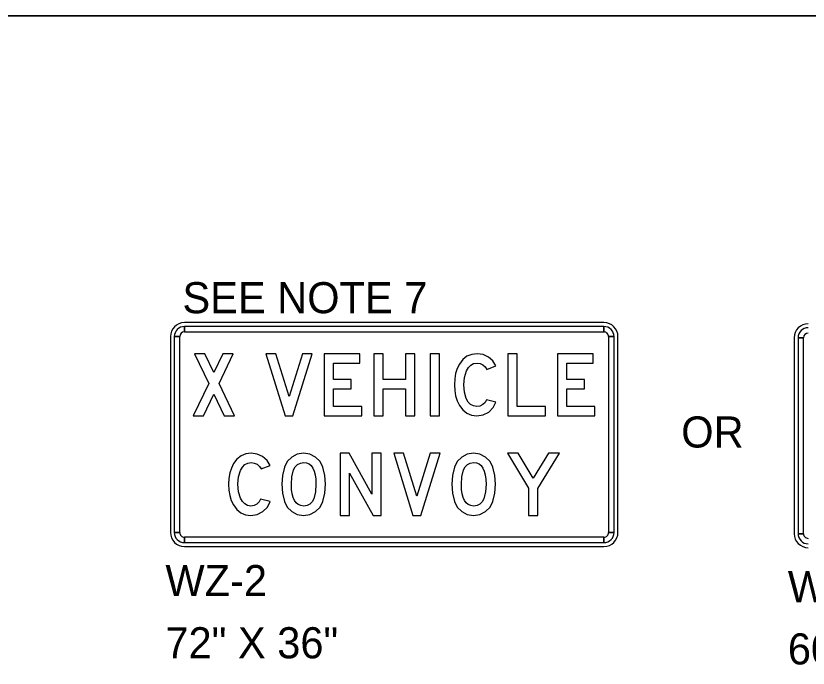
# Model space of a CAD drawing. Extents: x 1374027 to 1374537, y 380415 to 381405.
# Drawn here: x 1374115.53 to 1374130.82, y 381392.59 to 381405.17 of the extents above; entities that cross this region are included whole.
import ezdxf

# ---------------------------------------------------------------- set-up
doc = ezdxf.new("R2010")
doc.units = 0
doc.layers.add('DSN_DRFT_Junk-No-Plot', color=7, linetype='Continuous')
doc.layers.add('Working Level 1', color=7, linetype='Continuous')

msp = doc.modelspace()

# ---------------------------------------------------------------- linework, layer by layer
at = {"layer": 'DSN_DRFT_Junk-No-Plot'}
for points in [[(1374027.083, 381405.174), (1374197.083, 381405.174), (1374197.083, 381295.174), (1374027.083, 381295.174)], [(1374027.083, 381405.174), (1374027.083, 381295.174), (1374197.083, 381295.174), (1374197.083, 381405.174)]]:
    msp.add_lwpolyline(points, close=True, dxfattribs=at)
at = {"layer": 'Working Level 1'}
for p, q in [((1374126.884, 381399.254), (1374118.785, 381399.254)), ((1374118.785, 381399.074), (1374118.785, 381399.179)), ((1374126.884, 381399.179), (1374126.884, 381399.074)), ((1374118.515, 381398.984), (1374118.515, 381395.204)), ((1374118.59, 381398.984), (1374118.695, 381398.984)), ((1374126.974, 381398.984), (1374127.079, 381398.984)), ((1374127.154, 381395.204), (1374127.154, 381398.984)), ((1374130.555, 381398.961), (1374130.555, 381395.181)), ((1374130.63, 381398.961), (1374130.735, 381398.961)), ((1374118.695, 381395.204), (1374118.59, 381395.204)), ((1374127.079, 381395.204), (1374126.974, 381395.204)), ((1374130.735, 381395.181), (1374130.63, 381395.181)), ((1374118.785, 381395.009), (1374118.785, 381395.114)), ((1374126.884, 381395.114), (1374126.884, 381395.009)), ((1374118.785, 381394.934), (1374126.884, 381394.934))]:
    msp.add_line(p, q, dxfattribs=at)
for points in [[(1374126.884, 381399.179), (1374118.785, 381399.179), (1374118.785, 381399.074), (1374126.884, 381399.074), (1374126.884, 381399.179)], [(1374118.59, 381398.984), (1374118.59, 381395.204), (1374118.695, 381395.204), (1374118.695, 381398.984), (1374118.59, 381398.984)], [(1374127.079, 381395.204), (1374127.079, 381398.984), (1374126.974, 381398.984), (1374126.974, 381395.204), (1374127.079, 381395.204)], [(1374130.63, 381398.961), (1374130.63, 381395.181), (1374130.735, 381395.181), (1374130.735, 381398.961), (1374130.63, 381398.961)], [(1374119.754, 381397.454), (1374119.455, 381398.082), (1374119.729, 381398.654), (1374119.529, 381398.654), (1374119.355, 381398.292), (1374119.182, 381398.654), (1374118.981, 381398.654), (1374119.254, 381398.081), (1374118.953, 381397.454), (1374119.154, 381397.454), (1374119.354, 381397.871), (1374119.554, 381397.454)], [(1374121.253, 381398.654), (1374121.064, 381398.654), (1374120.806, 381397.825), (1374120.549, 381398.654), (1374120.36, 381398.654), (1374120.731, 381397.454), (1374120.88, 381397.454)], [(1374122.21, 381397.635), (1374121.666, 381397.635), (1374121.666, 381397.975), (1374122.005, 381397.975), (1374122.005, 381398.156), (1374121.666, 381398.156), (1374121.666, 381398.473), (1374122.173, 381398.473), (1374122.173, 381398.654), (1374121.484, 381398.654), (1374121.484, 381397.454), (1374122.21, 381397.454)], [(1374123.233, 381397.454), (1374123.233, 381398.654), (1374123.052, 381398.654), (1374123.052, 381398.156), (1374122.622, 381398.156), (1374122.622, 381398.654), (1374122.441, 381398.654), (1374122.441, 381397.454), (1374122.622, 381397.454), (1374122.622, 381397.975), (1374123.052, 381397.975), (1374123.052, 381397.454)], [(1374123.709, 381397.454), (1374123.709, 381398.654), (1374123.528, 381398.654), (1374123.528, 381397.454)], [(1374124.798, 381397.72), (1374124.616, 381397.766), (1374124.59, 381397.714), (1374124.546, 381397.672), (1374124.489, 381397.644), (1374124.427, 381397.635), (1374124.364, 381397.645), (1374124.31, 381397.673), (1374124.264, 381397.721), (1374124.227, 381397.788), (1374124.19, 381397.911), (1374124.178, 381398.054), (1374124.191, 381398.198), (1374124.229, 381398.321), (1374124.267, 381398.387), (1374124.313, 381398.435), (1374124.368, 381398.463), (1374124.433, 381398.473), (1374124.493, 381398.464), (1374124.547, 381398.44), (1374124.593, 381398.4), (1374124.624, 381398.35), (1374124.798, 381398.418), (1374124.739, 381398.515), (1374124.654, 381398.59), (1374124.55, 381398.638), (1374124.436, 381398.654), (1374124.33, 381398.641), (1374124.238, 381398.604), (1374124.159, 381398.541), (1374124.094, 381398.454), (1374124.051, 381398.367), (1374124.021, 381398.272), (1374124.003, 381398.168), (1374123.997, 381398.055), (1374124.003, 381397.942), (1374124.021, 381397.838), (1374124.05, 381397.743), (1374124.093, 381397.656), (1374124.157, 381397.568), (1374124.234, 381397.505), (1374124.325, 381397.466), (1374124.43, 381397.454), (1374124.552, 381397.472), (1374124.661, 381397.528), (1374124.747, 381397.613)], [(1374125.754, 381397.454), (1374125.754, 381397.635), (1374125.209, 381397.635), (1374125.209, 381398.654), (1374125.028, 381398.654), (1374125.028, 381397.454)], [(1374126.71, 381397.635), (1374126.166, 381397.635), (1374126.166, 381397.975), (1374126.505, 381397.975), (1374126.505, 381398.156), (1374126.166, 381398.156), (1374126.166, 381398.473), (1374126.673, 381398.473), (1374126.673, 381398.654), (1374125.985, 381398.654), (1374125.985, 381397.454), (1374126.71, 381397.454)], [(1374120.439, 381395.801), (1374120.257, 381395.847), (1374120.23, 381395.794), (1374120.186, 381395.752), (1374120.13, 381395.724), (1374120.067, 381395.715), (1374120.005, 381395.725), (1374119.95, 381395.754), (1374119.905, 381395.801), (1374119.868, 381395.868), (1374119.831, 381395.991), (1374119.819, 381396.134), (1374119.831, 381396.278), (1374119.869, 381396.401), (1374119.907, 381396.467), (1374119.954, 381396.515), (1374120.009, 381396.543), (1374120.073, 381396.553), (1374120.133, 381396.544), (1374120.188, 381396.52), (1374120.233, 381396.48), (1374120.265, 381396.43), (1374120.439, 381396.498), (1374120.38, 381396.595), (1374120.294, 381396.67), (1374120.19, 381396.718), (1374120.076, 381396.734), (1374119.971, 381396.721), (1374119.879, 381396.684), (1374119.8, 381396.621), (1374119.734, 381396.534), (1374119.692, 381396.447), (1374119.662, 381396.352), (1374119.644, 381396.248), (1374119.638, 381396.135), (1374119.643, 381396.022), (1374119.661, 381395.918), (1374119.691, 381395.823), (1374119.733, 381395.737), (1374119.797, 381395.648), (1374119.875, 381395.585), (1374119.966, 381395.547), (1374120.07, 381395.534), (1374120.192, 381395.553), (1374120.302, 381395.608), (1374120.388, 381395.693)], [(1374121.507, 381396.135), (1374121.494, 381396.306), (1374121.458, 381396.466), (1374121.404, 381396.575), (1374121.318, 381396.66), (1374121.209, 381396.715), (1374121.087, 381396.734), (1374120.965, 381396.715), (1374120.857, 381396.66), (1374120.771, 381396.574), (1374120.718, 381396.465), (1374120.681, 381396.305), (1374120.669, 381396.135), (1374120.681, 381395.965), (1374120.718, 381395.804), (1374120.771, 381395.695), (1374120.857, 381395.609), (1374120.965, 381395.553), (1374121.087, 381395.534), (1374121.209, 381395.553), (1374121.317, 381395.608), (1374121.403, 381395.693), (1374121.457, 381395.802), (1374121.494, 381395.963)], [(1374122.586, 381395.534), (1374122.586, 381396.734), (1374122.405, 381396.734), (1374122.405, 381395.945), (1374121.968, 381396.734), (1374121.794, 381396.734), (1374121.794, 381395.534), (1374121.975, 381395.534), (1374121.975, 381396.348), (1374122.426, 381395.534)], [(1374123.719, 381396.734), (1374123.529, 381396.734), (1374123.272, 381395.905), (1374123.014, 381396.734), (1374122.825, 381396.734), (1374123.197, 381395.534), (1374123.346, 381395.534)], [(1374124.788, 381396.135), (1374124.775, 381396.306), (1374124.739, 381396.466), (1374124.685, 381396.575), (1374124.599, 381396.66), (1374124.49, 381396.715), (1374124.368, 381396.734), (1374124.246, 381396.715), (1374124.138, 381396.66), (1374124.053, 381396.574), (1374123.999, 381396.465), (1374123.962, 381396.305), (1374123.95, 381396.135), (1374123.962, 381395.965), (1374123.999, 381395.804), (1374124.053, 381395.695), (1374124.138, 381395.609), (1374124.246, 381395.553), (1374124.368, 381395.534), (1374124.49, 381395.553), (1374124.598, 381395.608), (1374124.684, 381395.693), (1374124.738, 381395.802), (1374124.775, 381395.963)], [(1374126.025, 381396.734), (1374125.812, 381396.734), (1374125.518, 381396.255), (1374125.23, 381396.734), (1374125.019, 381396.734), (1374125.426, 381396.06), (1374125.426, 381395.534), (1374125.607, 381395.534), (1374125.607, 381396.055)], [(1374121.325, 381396.134), (1374121.315, 381395.988), (1374121.283, 381395.853), (1374121.254, 381395.796), (1374121.209, 381395.752), (1374121.152, 381395.724), (1374121.088, 381395.715), (1374121.032, 381395.722), (1374120.984, 381395.741), (1374120.943, 381395.774), (1374120.909, 381395.82), (1374120.883, 381395.879), (1374120.865, 381395.951), (1374120.854, 381396.036), (1374120.85, 381396.134), (1374120.861, 381396.279), (1374120.892, 381396.414), (1374120.921, 381396.471), (1374120.966, 381396.515), (1374121.023, 381396.543), (1374121.088, 381396.553), (1374121.144, 381396.546), (1374121.192, 381396.527), (1374121.232, 381396.494), (1374121.266, 381396.448), (1374121.292, 381396.389), (1374121.311, 381396.317), (1374121.322, 381396.232)], [(1374124.607, 381396.134), (1374124.596, 381395.988), (1374124.564, 381395.853), (1374124.535, 381395.796), (1374124.49, 381395.752), (1374124.434, 381395.724), (1374124.37, 381395.715), (1374124.313, 381395.722), (1374124.265, 381395.741), (1374124.224, 381395.774), (1374124.191, 381395.82), (1374124.164, 381395.879), (1374124.146, 381395.951), (1374124.135, 381396.036), (1374124.131, 381396.134), (1374124.142, 381396.279), (1374124.174, 381396.414), (1374124.202, 381396.471), (1374124.247, 381396.515), (1374124.304, 381396.543), (1374124.37, 381396.553), (1374124.425, 381396.546), (1374124.473, 381396.527), (1374124.514, 381396.494), (1374124.547, 381396.448), (1374124.573, 381396.389), (1374124.592, 381396.317), (1374124.603, 381396.232)], [(1374118.785, 381395.009), (1374126.884, 381395.009), (1374126.884, 381395.114), (1374118.785, 381395.114), (1374118.785, 381395.009)]]:
    msp.add_lwpolyline(points, close=True, dxfattribs=at)
for centre, radius, start, end in [((1374118.785, 381398.984), 0.27, 90.0002, 179.9998), ((1374126.884, 381398.984), 0.27, 0, 90.0002), ((1374118.785, 381398.984), 0.195, 90.0002, 179.9998), ((1374126.884, 381398.984), 0.195, 0, 90.0002), ((1374130.825, 381398.961), 0.27, 90.0002, 179.9998), ((1374130.825, 381398.961), 0.195, 90.0002, 179.9998), ((1374118.785, 381398.984), 0.09, 90.0002, 179.9998), ((1374126.884, 381398.984), 0.09, 0, 90.0002), ((1374130.825, 381398.961), 0.09, 90.0002, 179.9998), ((1374118.785, 381395.204), 0.27, 179.9998, 270.0001), ((1374118.785, 381395.204), 0.195, 179.9998, 270.0001), ((1374118.785, 381395.204), 0.09, 179.9998, 270.0001), ((1374126.884, 381395.204), 0.27, 270.0001, 0.0003), ((1374126.884, 381395.204), 0.195, 270.0001, 0.0003), ((1374126.884, 381395.204), 0.09, 270.0001, 0.0003), ((1374130.825, 381395.181), 0.27, 179.9998, 270.0001), ((1374130.825, 381395.181), 0.195, 179.9998, 270.0001), ((1374130.825, 381395.181), 0.09, 179.9998, 270.0001)]:
    msp.add_arc(centre, radius, start, end, dxfattribs=at)

# ---------------------------------------------------------------- texts
msp.add_text('SEE NOTE 7 ', height=0.6, dxfattribs=at).set_placement((1374118.748, 381399.435))
for s, p in [('OR', (1374128.375, 381396.844)), ('WZ-2', (1374118.419, 381393.976)), ('WZ-3', (1374130.433, 381393.858)), ('72" X 36"', (1374118.419, 381392.776)), ('60" X 36"', (1374130.433, 381392.658))]:
    msp.add_text(s, height=0.6, rotation=0, dxfattribs=at).set_placement(p)

doc.saveas('drawing.dxf')
